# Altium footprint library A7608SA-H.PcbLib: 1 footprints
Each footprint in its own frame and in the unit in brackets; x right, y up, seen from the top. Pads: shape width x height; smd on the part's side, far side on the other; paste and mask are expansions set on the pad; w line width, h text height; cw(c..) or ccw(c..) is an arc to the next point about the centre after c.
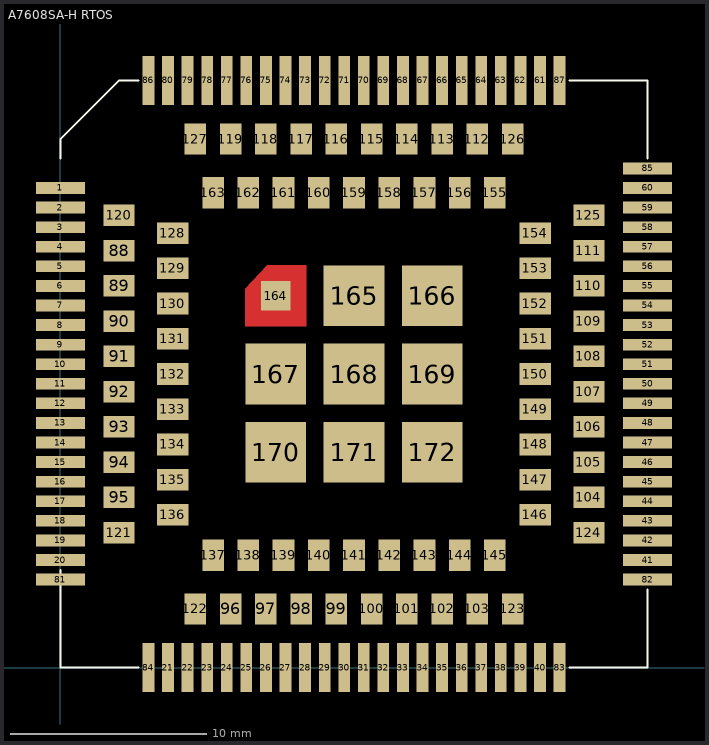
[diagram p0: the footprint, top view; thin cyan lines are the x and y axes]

## A7608SA-H RTOS [mm]
pads (172):
  rect 2.5x0.6 smd: 1(0,24.5) 2(0,23.5) 3(0,22.5) 4(0,21.5) 5(0,20.5) 6(0,19.5) 7(0,18.5) 8(0,17.5) 9(0,16.5) 10(0,15.5) 11(0,14.5) 12(0,13.5) 13(0,12.5) 14(0,11.5) 15(0,10.5) 16(0,9.5) 17(0,8.5) 18(0,7.5) 19(0,6.5) 20(0,5.5) 41(30,5.5) 42(30,6.5) 43(30,7.5) 44(30,8.5) 45(30,9.5) 46(30,10.5) 47(30,11.5) 48(30,12.5) 49(30,13.5) 50(30,14.5) 51(30,15.5) 52(30,16.5) 53(30,17.5) 54(30,18.5) 55(30,19.5) 56(30,20.5) 57(30,21.5) 58(30,22.5) 59(30,23.5) 60(30,24.5) 81(0,4.5) 82(30,4.5) 85(30,25.5)
  rect 0.6x2.5 smd: 21(5.5,0) 22(6.5,0) 23(7.5,0) 24(8.5,0) 25(9.5,0) 26(10.5,0) 27(11.5,0) 28(12.5,0) 29(13.5,0) 30(14.5,0) 31(15.5,0) 32(16.5,0) 33(17.5,0) 34(18.5,0) 35(19.5,0) 36(20.5,0) 37(21.5,0) 38(22.5,0) 39(23.5,0) 40(24.5,0) 61(24.5,30) 62(23.5,30) 63(22.5,30) 64(21.5,30) 65(20.5,30) 66(19.5,30) 67(18.5,30) 68(17.5,30) 69(16.5,30) 70(15.5,30) 71(14.5,30) 72(13.5,30) 73(12.5,30) 74(11.5,30) 75(10.5,30) 76(9.5,30) 77(8.5,30) 78(7.5,30) 79(6.5,30) 80(5.5,30) 83(25.5,0) 84(4.5,0) 86(4.5,30) 87(25.5,30)
  rect 1.6x1.1 smd: 88(3,21.3) 89(3,19.5) 90(3,17.7) 91(3,15.9) 92(3,14.1) 93(3,12.3) 94(3,10.5) 95(3,8.7) 104(27,8.7) 105(27,10.5) 106(27,12.3) 107(27,14.1) 108(27,15.9) 109(27,17.7) 110(27,19.5) 111(27,21.3) 120(3,23.1) 121(3,6.9) 124(27,6.9) 125(27,23.1) 128(5.75,22.2) 129(5.75,20.4) 130(5.75,18.6) 131(5.75,16.8) 132(5.75,15) 133(5.75,13.2) 134(5.75,11.4) 135(5.75,9.6) 136(5.75,7.8) 146(24.25,7.8) 147(24.25,9.6) 148(24.25,11.4) 149(24.25,13.2) 150(24.25,15) 151(24.25,16.8) 152(24.25,18.6) 153(24.25,20.4) 154(24.25,22.2)
  rect 1.1x1.6 smd: 96(8.7,3) 97(10.5,3) 98(12.3,3) 99(14.1,3) 100(15.9,3) 101(17.7,3) 102(19.5,3) 103(21.3,3) 112(21.3,27) 113(19.5,27) 114(17.7,27) 115(15.9,27) 116(14.1,27) 117(12.3,27) 118(10.5,27) 119(8.7,27) 122(6.9,3) 123(23.1,3) 126(23.1,27) 127(6.9,27) 137(7.8,5.75) 138(9.6,5.75) 139(11.4,5.75) 140(13.2,5.75) 141(15,5.75) 142(16.8,5.75) 143(18.6,5.75) 144(20.4,5.75) 145(22.2,5.75) 155(22.2,24.25) 156(20.4,24.25) 157(18.6,24.25) 158(16.8,24.25) 159(15,24.25) 160(13.2,24.25) 161(11.4,24.25) 162(9.6,24.25) 163(7.8,24.25)
  rect 1.5x1.5 smd: 164(11,19)
  rect 3.1x3.1 smd: 165(15,19) 166(19,19) 167(11,15) 168(15,15) 169(19,15) 170(11,11) 171(15,11) 172(19,11)
Top Layer:
  region: 12.55,17.45 9.45,17.45 9.45,19.363 10.562,20.55 12.55,20.55
Top Overlay:
  lines w0.1: 0,5 0,0 4,0 ; 0,26 0,27 3,30 4,30 ; 26,0 30,0 30,4 ; 26,30 30,30 30,26
3D body "a7600c_asm_190820.stp": height 2.5, standoff 0, extent 0,0 30,30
